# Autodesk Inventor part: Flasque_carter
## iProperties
Shininess: 64.0
Length Units: 11269
Angle Units: 11279
Time Units: 11290
Mass Units: 11283
Length Display Precision: 3
Angle Display Precision: 2
Compacted: True
Part Number: Flasque_carter
Document SubType Name: Modeling
Created: 2008-02
Material: Acier inoxydable - 440C
Designer: Pascal
Density: 0.0
Volumn: 0.0
Area: 0.0
PropertySet Name: Model Information
Control State: 0
Master: False
Checked Out: False
DESIGNATION: Flasque carter
Author: Pascal
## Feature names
1. Extrusion1
